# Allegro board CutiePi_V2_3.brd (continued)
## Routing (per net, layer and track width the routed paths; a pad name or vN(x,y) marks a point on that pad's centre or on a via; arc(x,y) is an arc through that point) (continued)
VBAT: length 21
  TOP w0.203: R3089.2 70.26,23.75 70.04,23.52 70.04,21.87 67.31,19.14 U597.17
  TOP w0.305: R3095.2 v1(57.82,23.88) ; R3100.2 v1(59.6,23.91)
  TOP w0.381: R3097.2 v1(72.55,12.06)
  L03 w0.508: v1(72.55,12.06) 72.55,13.37 v1(76.42,17.24) v1(77.44,17.24)
  vias: v1(68.2,27.43) v1(68.2,26.16) v1(69.47,27.43) v1(69.47,26.16) v1(70.74,44.07) v1(70.74,27.43) v1(70.74,26.16) v1(70.76,43.18) v1(71.77,44.06) v1(71.77,43.18) v1(72.01,27.43) v1(72.01,26.16)
VBAT_AD: length 8.9
  TOP w0.381: U18.14 62.7,41.46 63.01,41.15 65.02,41.15 65.63,41.75 R3053.1 C2525.1 R3154.1 R3052.1
VBAT_AD_C: length 69.4
  TOP w0.152: J24.94 54.66,97.84 51.94,95.12 51.94,80.14 v1(52.7,79.38) ; R3154.2 v1(68.85,43.29)
  L04 w0.145: v1(68.85,43.29) 68.85,43.93 65.79,46.99 58.56,46.99 57.4,48.14 57.4,50.55 53.09,54.86 53.09,76.33 53.34,76.58 53.34,78.74 v1(52.7,79.38)
VBUS: length 29.2
  TOP w0.305: R3101.1 v1(70.77,14.1) ; R3137.1 74.45,14.19 v1(74.36,14.1) 74.45,14 R3086.1
  TOP w0.381: v1(11.43,87.88) R3168.2 R3169.2 v1(11.43,86.36)
  TOP w0.508: FB9.2 29.09,17.05 v1(29.88,16.26)
  L04 w0.305: v1(63.5,9.91) 64.77,11.18 72.9,11.18 74.36,12.64 v1(74.36,14.1) 73.72,14.73 71.41,14.73 v1(70.77,14.1)
  vias: v1(12.7,81.66) v1(12.7,80.64) v1(12.7,79.63) v1(13.97,81.66) v1(13.97,80.64) v1(13.97,79.63) v1(15.37,81.66) v1(15.37,80.64) v1(15.37,79.63) v1(19.68,53.34) v1(19.68,52.07) v1(20.95,53.34) v1(20.95,52.07) v1(29.88,15.24) v1(30.89,16.26) v1(30.89,15.24) v1(31.91,16.26) v1(31.91,15.24) v1(61.37,4.36) v1(61.37,3.56) v1(62.39,4.36) v1(62.39,3.56) v1(63.41,4.36) v1(63.41,3.56) v1(67.56,93.09) v1(68.2,93.85) v1(68.45,104.52) v1(68.45,103.25) v1(68.45,101.98) v1(68.83,93.09) v1(69.72,104.52) v1(69.72,101.98)
VBUSA: length 5.9
  TOP w0.305: v1(15.78,45.21) 16.13,45.56 16.13,45.63 ; 16.13,45.63 v1(16.54,45.21) ; 16.13,45.63 U5.5
  TOP w0.381: R3058.2 8.67,88.36 v1(8.26,88.77)
  TOP w0.762: 12.1,49.98 J14.1 ; J14.1 12.1,51.92 ; J14.1 13.07,50.95
  vias: v1(16.51,55.88) v1(16.51,54.61) v1(17.78,55.88) v1(17.78,54.61) v1(39.12,44.96) v1(40.01,44.96)
VDDA: length 7
  TOP w0.305: FB7.2 66.44,34.44 C2479.1 C2474.1 63.74,34.87 63.43,35.18 62.21,35.18 61.4,35.99 U18.5
AMP_SHUTDOWN: length 44.8
  TOP w0.152: J24.45 60.22,88.24 60.71,87.76 61.72,87.76 v1(62.23,88.27) ; v1(74.93,104.78) 74.55,105.16 67.56,105.16 TP59.1
  TOP w0.254: R3145.1 64.96,100.87 R3061.2 ; R3061.2 66.97,100.87 67.06,100.96 Q6.1 ; R3061.2 66.29,101.6 66.42,101.73 66.42,103.25 TP59.1
  L03 w0.145: v1(74.93,104.78) 75.31,104.39 75.31,94.74 70.1,89.53 63.5,89.53 v1(62.23,88.27)
AU_IN: length 139.8
  TOP w0.152: R3184.2 C2517.2 37.59,17.4 v1(37.59,17.4) ; v1(69.85,93.34) 69.85,93.73 69.06,94.52 R127.1
  L04 w0.145: v1(69.85,93.34) 69.85,89.79 70.99,88.65 70.99,79.63 82.55,68.07 82.55,43.05 78.99,39.5 78.99,10.6 76.77,8.38 60.33,8.38 59.56,9.14 56.13,9.14 54.23,11.05 43.94,11.05 v1(37.59,17.4)
BL_EN: length 103.2
  TOP w0.152: R3197.1 64.11,84.45 v1(62.23,84.45) ; v1(42.45,17.02) R88.2
  L03 w0.145: v1(52.7,89.53) 53.34,90.17 55.75,90.17 56.13,89.79 56.13,86.87 56.64,86.36 59.69,86.36 60.58,85.47 61.21,85.47 v1(62.23,84.45)
  L04 w0.145: v1(42.45,17.02) 41.02,17.02 33.15,24.89 33.15,35.05 35.31,37.21 35.31,73.41 51.44,89.53 v1(52.7,89.53)
BOOST_EN: length 46.7
  TOP w0.152: v1(65.42,44.19) 64.65,43.42 U18.11 ; v1(59.1,16.65) 59.75,16 61.76,16 62.04,16.29 R3094.1 63.13,16.64 63.8,15.97 U597.24
  L04 w0.145: v1(65.42,44.19) 64.91,44.7 64.91,45.45 64.52,45.85 60.96,45.85 56.9,41.78 56.9,35.69 56.13,34.92 56.13,19.62 v1(59.1,16.65)
BT_NDIS: length 3
  TOP w0.152: J24.91 61.75,97.44 TP78.1
CAM0_CN: length 80.1
  TOP w0.109: v1(70.64,108.17) 70.87,108.4 70.87,108.58 70.77,108.68 J26.8 ; v1(20.32,86.86) 20.54,87.08 21.66,87.08 21.7,87.04 J25.40
  L03 w0.114: v1(20.32,86.86) 20.51,87.05 20.96,87.05 21.29,87.37 21.29,92.76 17.4,96.65 17.4,100.7 21.65,104.95 58.56,104.95 63.7,110.1 64.01,110.1 64.24,110.33 64.24,110.64 64.47,110.87 65.15,110.87 65.37,110.66 65.7,110.66 65.91,110.87 66.29,110.87 66.51,110.66 66.84,110.66 67.06,110.87 70.48,110.87 70.85,110.5 70.85,108.38 v1(70.64,108.17)
CAM0_CP: length 80.1
  TOP w0.109: v1(20.32,87.62) 20.54,87.4 21.66,87.4 21.7,87.44 J25.42 ; v1(71.4,108.17) 71.19,108.37 71.19,108.53 71.27,108.61 J26.9
  L03 w0.114: v1(71.4,108.17) 71.18,108.38 71.18,110.64 70.62,111.2 64.34,111.2 58.42,105.28 21.51,105.28 17.07,100.84 17.07,96.51 20.95,92.62 20.95,87.5 20.83,87.38 20.57,87.38 v1(20.32,87.62)
CAM0_DN0: length 80.3
  TOP w0.109: J26.2 67.77,108.64 67.86,108.54 67.86,108.39 v1(67.64,108.17) ; v1(20.32,84.46) 20.54,84.68 21.66,84.68 21.7,84.64 J25.28
  L03 w0.114: v1(20.32,84.46) 20.57,84.46 20.87,84.75 21.76,84.75 22.43,85.42 22.43,93.14 18.54,97.03 18.54,100.2 21.77,103.43 59.03,103.43 59.25,103.21 59.58,103.21 59.79,103.43 60.12,103.43 60.88,104.19 61.04,104.19 61.38,103.85 61.81,103.85 62.25,104.29 62.25,104.72 61.91,105.06 61.91,105.22 62.16,105.46 62.32,105.46 62.65,105.13 63.09,105.13 63.53,105.56 63.53,106 63.19,106.33 63.19,106.5 63.43,106.74 63.59,106.74 63.93,106.4 64.36,106.4 64.8,106.84 64.8,107.27 64.46,107.61 64.46,107.77 64.62,107.92 64.91,107.92 65.05,108.07 65.05,108.36 65.66,108.97 65.99,108.97 66.21,108.75 66.54,108.75 66.75,108.97 67.73,108.97 67.85,108.85 67.85,108.38 v1(67.64,108.17)
CAM0_DN1: length 81.7
  TOP w0.109: J25.34 22.84,85.84 22.88,85.88 23.91,85.88 v1(24.13,85.66) ; J26.5 69.27,108.6 69.35,108.52 69.35,107.28 v1(69.14,107.06)
  L03 w0.114: v1(69.14,107.06) 69.35,106.85 69.35,106.18 69.04,105.87 65.74,105.87 62.05,102.18 58.18,102.18 57.87,101.88 57.87,101.28 57.75,101.17 57.41,101.17 57.3,101.28 57.3,101.88 56.99,102.18 56.37,102.18 56.07,101.88 56.07,101.28 55.95,101.17 55.61,101.17 55.49,101.28 55.49,101.88 55.19,102.18 54.57,102.18 54.26,101.88 54.26,101.28 54.15,101.17 53.8,101.17 53.69,101.28 53.69,101.88 53.38,102.18 52.77,102.18 52.46,101.88 52.46,101.28 52.34,101.17 52,101.17 51.89,101.28 51.89,101.88 51.58,102.18 21.71,102.18 19.43,99.91 19.43,97.2 22.39,94.23 23.54,94.23 24.05,93.72 24.05,88.15 23.16,87.26 23.16,86.18 23.47,85.88 23.91,85.88 v1(24.13,85.66)
CAM0_DP0: length 80.3
  TOP w0.109: v1(68.4,108.17) 68.18,108.38 68.18,108.57 68.27,108.65 J26.3 ; v1(20.32,85.22) 20.54,85 21.66,85 21.7,85.04 J25.30
  L03 w0.114: v1(68.4,108.17) 68.18,108.38 68.18,108.98 67.87,109.3 65.52,109.3 64.13,107.91 64.13,107.47 64.47,107.14 64.47,106.97 64.23,106.73 64.07,106.73 63.73,107.07 63.29,107.07 62.86,106.63 62.86,106.2 63.19,105.86 63.19,105.7 62.95,105.46 62.79,105.46 62.45,105.79 62.02,105.79 61.58,105.36 61.58,104.92 61.92,104.59 61.92,104.42 61.68,104.18 61.52,104.18 61.18,104.52 60.74,104.52 59.99,103.76 21.63,103.76 18.21,100.34 18.21,96.89 22.1,93 22.1,85.56 21.62,85.08 20.71,85.08 20.57,85.22 v1(20.32,85.22)
CAM0_DP1: length 81.7
  TOP w0.109: J26.6 69.77,108.6 69.68,108.52 69.68,107.28 v1(69.9,107.06) ; J25.36 22.84,86.24 22.88,86.2 23.91,86.2 v1(24.13,86.42)
  L03 w0.114: v1(24.13,86.42) 23.91,86.21 23.61,86.21 23.5,86.32 23.5,87.12 24.38,88.01 24.38,93.85 23.67,94.56 22.53,94.56 19.76,97.33 19.76,99.77 21.84,101.85 51.44,101.85 51.56,101.74 51.56,101.15 51.86,100.84 52.48,100.84 52.79,101.15 52.79,101.74 52.9,101.85 53.25,101.85 53.36,101.74 53.36,101.15 53.67,100.84 54.28,100.84 54.59,101.15 54.59,101.74 54.71,101.85 55.05,101.85 55.16,101.74 55.16,101.15 55.47,100.84 56.09,100.84 56.4,101.15 56.4,101.74 56.51,101.85 56.85,101.85 56.97,101.74 56.97,101.15 57.27,100.84 57.89,100.84 58.2,101.15 58.2,101.74 58.31,101.85 62.19,101.85 65.1,104.76 65.41,104.76 65.64,105 65.64,105.3 65.87,105.54 66.2,105.54 66.42,105.32 66.75,105.32 66.96,105.54 67.44,105.54 67.65,105.32 67.98,105.32 68.2,105.54 69.17,105.54 69.68,106.05 69.68,106.85 v1(69.9,107.06)
CAM0_IO0: length 40.9
  TOP w0.152: J24.27 59.88,84.64 60.07,84.45 v1(60.96,84.45) ; v1(74.93,106.05) 75.27,106.38 J26.17
  L03 w0.145: v1(60.96,84.45) 61.34,84.45 61.85,83.95 63.12,83.95 65.66,86.49 67.31,86.49 68.96,88.14 75.18,88.14 77.22,90.17 77.22,102.62 76.07,103.76 76.07,104.9 v1(74.93,106.05)
CAM0_IO1: length 48
  TOP w0.152: v1(55.24,84.2) 55.29,84.24 J24.26 ; v1(76.2,106.05) 75.77,106.48 J26.18
  L03 w0.145: v1(76.2,106.05) 76.77,105.47 76.77,104.33 77.72,103.38 77.72,88.65 73.79,84.71 67.06,84.71 66.29,83.95 64.52,83.95 63.12,82.55 60.2,82.55 59.56,83.19 58.17,83.19 57.53,83.82 55.63,83.82 v1(55.24,84.2)
CAM1_CN: length 85.9
  TOP w0.109: J11.8 83.8,80.75 83.71,80.66 82.99,80.66 v1(82.71,80.95) ; J25.27 25.92,84.64 25.96,84.68 30.02,84.68 30.61,85.27 33.44,85.27 v1(33.66,85.05)
  L03 w0.114: v1(82.71,80.95) 82.99,80.67 83.91,80.67 86.34,78.24 86.34,71.91 84.54,70.1 51.73,70.1 50.48,71.35 50.48,71.78 50.76,72.06 50.76,72.22 50.52,72.46 50.35,72.46 50.08,72.19 49.65,72.19 49.21,72.62 49.21,73.06 49.48,73.33 49.48,73.49 49.24,73.74 49.08,73.74 48.81,73.46 48.37,73.46 47.93,73.9 47.93,74.34 48.21,74.61 48.21,74.77 47.96,75.01 47.8,75.01 47.53,74.74 47.09,74.74 46.66,75.18 46.66,75.61 46.93,75.88 46.93,76.04 46.69,76.29 46.53,76.29 46.25,76.01 45.82,76.01 36.56,85.27 33.87,85.27 v1(33.66,85.05)
CAM1_CP: length 85.8
  TOP w0.109: J25.29 25.92,85.04 25.96,85 27.25,85 27.46,85.21 27.66,85.21 27.86,85 28.26,85 28.46,85.21 28.67,85.21 28.87,85 29.07,85 29.28,85.21 29.48,85.21 29.68,85 29.89,85 30.48,85.6 30.68,85.6 30.89,85.8 31.09,85.8 31.29,85.6 31.5,85.6 31.7,85.8 31.9,85.8 32.11,85.6 32.33,85.6 32.54,85.8 32.74,85.8 32.94,85.6 33.44,85.6 v1(33.66,85.82) ; J11.9 83.83,80.25 83.75,80.34 82.99,80.34 v1(82.71,80.06)
  L03 w0.114: v1(82.71,80.06) 82.99,80.34 83.78,80.34 86.01,78.1 86.01,72.04 84.4,70.43 51.87,70.43 50.81,71.49 50.81,71.65 51.09,71.92 51.09,72.36 50.65,72.79 50.22,72.79 49.94,72.52 49.78,72.52 49.54,72.76 49.54,72.92 49.81,73.2 49.81,73.63 49.38,74.07 48.94,74.07 48.67,73.79 48.51,73.79 48.26,74.04 48.26,74.2 48.54,74.47 48.54,74.91 48.1,75.34 47.67,75.34 47.39,75.07 47.23,75.07 46.99,75.31 46.99,75.47 47.26,75.75 47.26,76.18 46.83,76.62 46.39,76.62 46.12,76.34 45.96,76.34 36.7,85.6 33.87,85.6 v1(33.66,85.82)
CAM1_DN0: length 88.6
  TOP w0.109: J25.15 25.92,82.24 25.96,82.28 33.44,82.28 v1(33.66,82.06) ; v1(82.71,83.95) 83.04,83.62 83.39,83.62 83.44,83.66 83.73,83.66 83.81,83.75 J11.2
  L03 w0.114: v1(33.66,82.06) 33.87,82.28 35.2,82.28 49.61,67.87 85.65,67.87 88.37,70.59 88.37,79.43 84.14,83.66 82.99,83.66 v1(82.71,83.95)
CAM1_DN1: length 87.2
  TOP w0.109: J11.5 83.81,82.25 83.73,82.16 83.57,82.16 81.85,82.16 v1(81.57,82.45) ; J25.21 25.92,83.44 25.96,83.48 30.34,83.48 30.61,83.75 35.34,83.75 v1(35.56,83.53)
  L03 w0.114: v1(81.57,82.45) 81.85,82.16 83.99,82.16 87.36,78.79 87.36,71.23 85.14,69.01 51.04,69.01 36.31,83.75 35.78,83.75 v1(35.56,83.53)
CAM1_DN2: length 87.4
  TOP w0.109: v1(35.56,86.71) 35.34,86.92 30.23,86.92 29.19,85.88 25.96,85.88 25.92,85.84 J25.33 ; v1(81.57,79.45) 81.85,79.16 83.73,79.16 83.82,79.25 J11.11
  L03 w0.114: v1(81.57,79.45) 81.84,79.17 84.06,79.17 85.34,77.88 85.34,72.56 84.03,71.25 55.79,71.25 52.62,74.42 50.21,74.42 46.85,77.78 46.69,77.78 46.46,77.55 46.02,77.55 45.59,77.98 45.59,78.42 45.82,78.65 45.82,78.81 45.57,79.05 45.41,79.05 45.18,78.82 44.75,78.82 44.31,79.26 44.31,79.7 44.54,79.93 44.54,80.09 44.3,80.33 44.14,80.33 43.91,80.1 43.47,80.1 43.04,80.54 43.04,80.97 43.27,81.2 43.27,81.36 43.02,81.6 42.86,81.6 42.63,81.37 42.2,81.37 41.76,81.81 41.76,82.25 41.99,82.48 41.99,82.64 41.75,82.88 41.59,82.88 41.36,82.65 40.92,82.65 40.49,83.09 40.49,83.52 40.72,83.75 40.72,83.91 40.47,84.16 40.31,84.16 40.08,83.93 39.65,83.93 39.21,84.36 39.21,84.8 39.44,85.03 39.44,85.19 39.2,85.43 39.04,85.43 38.81,85.2 38.37,85.2 37.93,85.64 37.93,86.07 38.16,86.3 38.16,86.46 37.71,86.92 36.17,86.92 35.96,86.71 v1(35.56,86.71)
CAM1_DN3: length 87.1
  TOP w0.109: v1(82.84,77.95) 83.12,77.66 83.73,77.66 83.81,77.75 J11.14 ; v1(33.66,88.23) 33.44,88.45 29.98,88.45 28.61,87.08 25.96,87.08 25.92,87.04 J25.39
  L03 w0.114: v1(82.84,77.95) 83.11,77.67 83.86,77.67 84.45,77.08 84.45,74.69 83.86,74.1 82.61,74.1 81.08,72.57 56.76,72.57 53.51,75.82 50.71,75.82 44.49,82.04 44.49,82.48 45.33,83.32 45.33,83.48 45.09,83.73 44.93,83.73 44.09,82.88 43.65,82.88 43.21,83.32 43.21,83.75 44.06,84.6 44.06,84.76 43.82,85 43.66,85 42.81,84.16 42.38,84.16 41.94,84.59 41.94,85.03 42.78,85.87 42.78,86.03 42.54,86.28 42.38,86.28 41.54,85.43 41.1,85.43 40.66,85.87 40.66,86.3 41.51,87.15 41.51,87.31 41.27,87.55 41.1,87.55 40.26,86.71 39.83,86.71 39.39,87.14 39.39,87.58 40.23,88.42 40.23,88.59 39.99,88.83 39.83,88.83 38.98,87.98 38.55,87.98 38.09,88.45 34.27,88.45 34.05,88.23 v1(33.66,88.23)
CAM1_DP0: length 88.6
  TOP w0.109: v1(82.71,83.06) 82.94,83.29 83.53,83.29 83.57,83.34 83.73,83.34 83.81,83.25 J11.3 ; J25.17 25.92,82.64 25.96,82.6 27.75,82.6 27.95,82.81 28.15,82.81 28.36,82.6 28.56,82.6 28.76,82.81 28.97,82.81 29.17,82.6 29.37,82.6 29.58,82.81 29.78,82.81 29.98,82.6 30.19,82.6 30.39,82.81 30.59,82.81 30.79,82.6 31,82.6 31.2,82.81 31.4,82.81 31.61,82.6 31.81,82.6 32.01,82.81 32.22,82.81 32.42,82.6 32.62,82.6 32.83,82.81 33.03,82.81 33.23,82.6 33.44,82.6 v1(33.66,82.82)
  L03 w0.114: v1(82.71,83.06) 82.99,83.33 84,83.33 88.04,79.29 88.04,70.73 85.51,68.2 49.74,68.2 35.34,82.61 33.87,82.61 v1(33.66,82.82)
CAM1_DP1: length 87.1
  TOP w0.109: v1(81.57,81.56) 81.85,81.84 83.44,81.84 83.73,81.84 83.81,81.75 J11.6 ; J25.23 25.92,83.84 25.96,83.8 28.58,83.8 28.79,84.01 28.99,84.01 29.19,83.8 29.4,83.8 29.6,84.01 29.8,84.01 30.01,83.8 30.21,83.8 30.48,84.07 30.68,84.07 30.89,84.28 31.09,84.28 31.29,84.07 31.5,84.07 31.7,84.28 31.9,84.28 32.11,84.07 32.31,84.07 32.51,84.28 32.72,84.28 32.92,84.07 33.12,84.07 33.32,84.28 33.53,84.28 33.73,84.07 35.34,84.07 v1(35.56,84.29)
  L03 w0.114: v1(81.57,81.56) 81.84,81.83 83.85,81.83 87.03,78.65 87.03,71.37 85,69.34 51.18,69.34 36.45,84.08 35.78,84.08 v1(35.56,84.29)
CAM1_DP2: length 87.3
  TOP w0.109: v1(81.57,78.56) 81.85,78.84 83.72,78.84 83.81,78.75 J11.12 ; J25.35 25.92,86.24 25.96,86.2 29.05,86.2 29.5,86.65 29.5,86.94 29.65,87.08 29.93,87.08 30.1,87.25 30.3,87.25 30.51,87.45 30.71,87.45 30.91,87.25 31.11,87.25 31.32,87.45 31.52,87.45 31.72,87.25 31.93,87.25 32.13,87.45 32.33,87.45 32.54,87.25 32.74,87.25 32.94,87.45 33.15,87.45 33.35,87.25 33.55,87.25 33.76,87.45 33.96,87.45 34.16,87.25 35.34,87.25 v1(35.56,87.47)
  L03 w0.114: v1(81.57,78.56) 81.85,78.84 83.92,78.84 85.01,77.75 85.01,72.69 83.9,71.58 55.93,71.58 52.76,74.75 50.34,74.75 46.99,78.11 46.55,78.11 46.32,77.88 46.16,77.88 45.92,78.12 45.92,78.28 46.15,78.51 46.15,78.95 45.71,79.38 45.28,79.38 45.05,79.15 44.88,79.15 44.64,79.4 44.64,79.56 44.87,79.79 44.87,80.22 44.44,80.66 44,80.66 43.77,80.43 43.61,80.43 43.37,80.67 43.37,80.83 43.6,81.06 43.6,81.5 43.16,81.94 42.72,81.94 42.49,81.7 42.33,81.71 42.09,81.95 42.09,82.11 42.32,82.34 42.32,82.77 41.88,83.21 41.45,83.21 41.22,82.98 41.06,82.98 40.82,83.22 40.82,83.38 41.05,83.61 41.05,84.05 40.61,84.49 40.17,84.49 39.94,84.26 39.78,84.26 39.54,84.5 39.54,84.66 39.77,84.89 39.77,85.32 39.33,85.76 38.9,85.76 38.67,85.53 38.51,85.53 38.26,85.77 38.26,85.93 38.49,86.17 38.49,86.6 37.84,87.25 36.17,87.25 35.96,87.47 v1(35.56,87.47)
CAM1_DP3: length 87
  TOP w0.109: v1(82.84,77.06) 83.12,77.34 83.44,77.34 83.73,77.34 83.81,77.25 J11.15 ; v1(33.66,88.99) 33.44,88.77 33.1,88.77 32.89,88.98 32.69,88.98 32.49,88.77 32.28,88.77 32.08,88.98 31.88,88.98 31.67,88.77 31.47,88.77 31.27,88.98 31.06,88.98 30.86,88.77 30.66,88.77 30.45,88.98 30.25,88.98 30.05,88.77 29.84,88.77 29.7,88.63 29.41,88.63 29.27,88.49 29.27,88.2 29.13,88.05 28.84,88.05 28.7,87.91 28.7,87.62 28.48,87.4 25.96,87.4 25.92,87.44 J25.41
  L03 w0.114: v1(82.84,77.06) 83.12,77.34 83.73,77.34 84.12,76.94 84.12,74.83 83.72,74.43 82.47,74.43 80.94,72.9 56.9,72.9 53.64,76.15 50.85,76.15 44.82,82.18 44.82,82.34 45.66,83.19 45.66,83.62 45.23,84.06 44.79,84.06 43.95,83.21 43.79,83.21 43.55,83.45 43.55,83.62 44.39,84.46 44.39,84.9 43.95,85.33 43.52,85.33 42.67,84.49 42.51,84.49 42.27,84.73 42.27,84.89 43.11,85.74 43.11,86.17 42.68,86.61 42.24,86.61 41.4,85.76 41.24,85.76 40.99,86.01 40.99,86.17 41.84,87.01 41.84,87.45 41.4,87.88 40.97,87.88 40.12,87.04 39.96,87.04 39.72,87.28 39.72,87.44 40.56,88.29 40.56,88.72 40.13,89.16 39.69,89.16 38.85,88.31 38.69,88.31 38.22,88.78 34.27,88.78 34.05,88.99 v1(33.66,88.99)
CAM1_IO0: length 36.5
  TOP w0.152: J11.17 83.87,76.25 83.82,76.2 80.01,76.2 v1(80.01,76.2) ; J24.34 55.36,85.84 v1(55.24,85.72)
  L03 w0.145: v1(55.24,85.72) 54.74,85.22 54.74,82.93 55.12,82.55 56.39,82.55 57.66,81.28 59.69,81.28 60.07,80.9 75.31,80.9 v1(80.01,76.2)
CAM1_IO1: length 42.2
  TOP w0.152: J11.18 82.1,75.75 81.92,75.56 79.38,75.56 v1(78.74,76.2) ; v1(55.24,89.53) 55.55,89.84 J24.54
  L03 w0.145: v1(78.74,76.2) 74.55,80.39 60.96,80.39 60.58,80.01 57.91,80.01 56.64,81.28 54.99,81.28 54.23,82.04 54.23,86.11 54.61,86.49 54.61,88.9 v1(55.24,89.53)
CAM_GPIO: length 4.1
  TOP w0.152: J24.97 60.16,98.64 61.21,99.69 61.21,100.2 TP79.1
CHARGE_EN: length 43.6
  TOP w0.152: U18.12 64,44.04 v1(64.15,44.19) ; v1(59.1,15.38) 59.75,14.73 61.76,14.73 62.04,15.02 R3096.1 62.24,15.57 U597.25
  L04 w0.145: v1(59.1,15.38) 59.72,16 59.72,16.98 56.77,19.94 56.77,34.8 58.29,36.32 58.29,41.15 61.85,44.7 63.64,44.7 v1(64.15,44.19)
CM_1V8: length 2.7
  TOP w0.305: v1(89.15,41.15) 88.91,40.9 J21.3 v1(87.43,40.9)
  TOP w0.381: R3057.1 v1(83.09,40.39)
  vias: v1(57.15,97.16) v1(58.42,97.16) v1(80.01,107.31) v1(80.01,106.05) v1(81.28,107.31) v1(81.28,106.05)
CM_3V3: length 13.5
  TOP w0.254: v1(80.01,74.93) 80.14,74.8 R16.1 ; C385.1 74.07,89.72 74.01,89.66 U57.13 ; R17.1 80.26,73.41 v1(80.01,73.66)
  TOP w0.305: R3167.1 v1(78.23,90.42) ; J21.1 87.09,41.5 86.79,41.2 J21.2 v1(84.58,41.2) v1(83.82,41.2) ; v1(78.11,107.95) 77.77,108.29 J26.22 ; R370.1 v1(78.23,84.07) ; v1(74.93,90.17) C385.1
  TOP w0.381: R3165.2 v1(67.44,85.34) ; R3166.2 v1(67.44,84.07)
  vias: v1(14.1,86.49) v1(15.24,86.49) v1(15.24,85.47) v1(53.98,95.89) v1(55.24,95.89) v1(57.15,95.89) v1(58.42,95.89) v1(62.23,90.81) v1(63.5,92.08) v1(63.5,90.81) v1(82.8,73.15) v1(83.44,72.52) v1(84.07,73.15)
DSI1_CN: length 108.5
  TOP w0.109: v1(86.36,37.46) 86.22,37.6 J21.14 ; v1(30.23,96.5) 30.08,96.65 28.96,96.65 28.89,96.72 25.99,96.72 25.92,96.64 J25.87
  L03 w0.114: v1(30.23,96.5) 30.01,96.71 29.49,96.71 29.34,96.56 29.34,92.46 30.05,91.74 30.05,80.19 48.46,61.77 48.46,58.22 56.08,50.6 56.08,48.06 61.85,42.29 71.75,42.29 72.41,41.64 72.57,41.64 72.97,42.04 73.4,42.04 73.84,41.6 73.84,41.17 73.44,40.77 73.44,40.61 73.68,40.36 73.84,40.36 74.24,40.76 74.68,40.76 75.11,40.33 75.11,39.89 74.71,39.49 74.71,39.33 74.96,39.09 75.12,39.09 75.52,39.49 75.95,39.49 76.39,39.05 76.39,38.62 75.99,38.22 75.99,38.06 76.96,37.08 78.54,37.08 78.75,37.29 78.95,37.29 79.15,37.08 79.36,37.08 79.56,37.29 79.76,37.29 79.97,37.08 80.17,37.08 80.39,37.3 80.61,37.3 80.83,37.08 81.06,37.08 81.27,37.3 81.5,37.3 81.72,37.08 81.95,37.08 82.16,37.3 82.39,37.3 82.61,37.08 82.84,37.08 83.05,37.3 83.28,37.3 83.5,37.08 83.73,37.08 83.94,37.3 84.17,37.3 84.39,37.08 84.62,37.08 84.83,37.3 85.06,37.3 85.28,37.08 85.5,37.08 85.64,36.95 86.62,36.95 86.74,37.07 86.74,37.35 86.62,37.46 v1(86.36,37.46)
DSI1_CP: length 108.6
  TOP w0.109: v1(87.24,37.46) 87.4,37.3 J21.15 ; J25.89 29.02,97.04 29.09,96.97 29.94,96.97 v1(30.23,97.26)
  L03 w0.114: v1(87.24,37.46) 87.07,37.28 87.07,36.93 86.76,36.62 85.5,36.62 85.37,36.75 76.83,36.75 75.66,37.92 75.66,38.35 76.06,38.75 76.06,38.92 75.82,39.16 75.66,39.16 75.26,38.76 74.82,38.76 74.38,39.19 74.38,39.63 74.78,40.03 74.78,40.19 74.54,40.43 74.38,40.43 73.98,40.03 73.54,40.03 73.11,40.47 73.11,40.91 73.51,41.31 73.51,41.47 73.27,41.71 73.1,41.71 72.7,41.31 72.27,41.31 71.62,41.96 61.71,41.96 55.75,47.92 55.75,50.46 48.13,58.08 48.13,61.64 29.72,80.05 29.72,91.61 29.01,92.32 29.01,96.7 29.35,97.04 30.01,97.04 v1(30.23,97.26)
DSI1_DN0: length 108.6
  TOP w0.109: v1(87.25,38.86) 87.12,38.86 86.96,38.7 86.96,38.38 87.1,38.25 87.53,38.25 87.78,38.5 J21.11 ; J25.75 25.92,94.24 25.96,94.28 26.12,94.28 26.37,94.02 30.18,94.02 v1(30.35,93.85)
  L03 w0.114: v1(30.35,93.85) 30.57,94.07 31.05,94.07 31.5,93.62 31.5,80.43 49.4,62.53 49.4,58.84 58.79,49.45 69.93,49.45 75.26,44.12 75.26,43.96 74.54,43.24 74.54,42.81 74.98,42.37 75.41,42.37 76.13,43.09 76.29,43.09 76.53,42.85 76.53,42.69 75.82,41.97 75.82,41.53 76.25,41.1 76.69,41.1 77.4,41.81 77.57,41.81 78.31,41.07 78.31,38.33 78.62,38.02 79.23,38.02 79.54,38.33 79.54,40.32 79.66,40.44 80,40.44 80.11,40.32 80.11,38.33 80.42,38.02 86.59,38.02 86.9,38.33 86.9,38.64 87.12,38.86 v1(87.25,38.86)
DSI1_DN1: length 107.8
  TOP w0.109: v1(27.3,95.25) 27.12,95.43 25.87,95.43 25.86,95.44 J25.81 ; J21.17 87.19,36.7 86.99,36.5 86.99,36.16 87.09,36.06 v1(87.24,36.06)
  L03 w0.114: v1(27.3,95.25) 27.52,95.47 27.75,95.47 27.86,95.35 27.86,91.3 28.45,90.72 28.45,87.06 28.33,86.95 27.61,86.95 27.3,86.64 27.3,86.02 27.61,85.72 28.33,85.72 28.45,85.6 28.45,85.26 28.33,85.14 27.61,85.14 27.3,84.84 27.3,84.22 27.61,83.91 28.33,83.91 28.45,83.8 28.45,83.46 28.33,83.34 27.61,83.34 27.3,83.03 27.3,82.42 27.61,82.11 28.33,82.11 28.45,81.99 28.45,79.54 46.23,61.76 46.23,55.03 61,40.26 70.61,40.26 75.65,35.23 86.66,35.23 87.03,35.59 87.03,35.85 v1(87.24,36.06)
DSI1_DN2: length 109.1
  TOP w0.109: J25.93 25.92,97.84 25.96,97.88 26.33,97.88 v1(26.54,97.66) ; J21.20 85.86,35.8 86.23,35.43 86.56,35.43 86.66,35.32 86.66,34.78 86.56,34.67 v1(86.36,34.67)
  L03 w0.114: v1(26.54,97.66) 26.33,97.88 25.74,97.88 25.48,97.61 25.48,80.19 45.34,60.33 45.34,52.83 60.96,37.21 71.59,37.21 74.89,33.91 79.59,33.91 79.8,34.12 80.03,34.12 80.25,33.91 80.47,33.91 80.69,34.12 80.92,34.12 81.14,33.91 81.36,33.91 81.58,34.12 81.81,34.12 82.02,33.91 82.25,33.91 82.47,34.12 82.7,34.12 82.91,33.91 83.14,33.91 83.36,34.12 83.59,34.12 83.8,33.91 84.03,33.91 84.25,34.12 84.48,34.12 84.69,33.91 85.17,33.91 85.39,34.12 85.62,34.12 85.83,33.91 86.23,33.91 86.7,34.38 86.7,34.55 86.59,34.67 v1(86.36,34.67)
DSI1_DN3: length 108.7
  TOP w0.109: v1(86.36,40.01) 86.61,40.01 86.74,39.88 86.74,39.55 86.59,39.4 J21.8 ; v1(20.32,97.66) 20.54,97.88 21.66,97.88 21.7,97.84 J25.94
  L03 w0.114: v1(86.36,40.01) 86.67,40.32 86.67,40.45 85.09,42.04 79.04,42.04 69.84,51.23 59.05,51.23 51.82,58.46 51.82,61.85 32.44,81.23 32.44,97.65 30.14,99.95 24.51,99.95 23.02,98.45 23.02,98.17 22.87,98.02 22.58,98.02 22.44,97.88 22.15,97.88 21.95,97.68 21.74,97.68 21.54,97.88 20.54,97.88 v1(20.32,97.66)
DSI1_DP0: length 108.7
  TOP w0.109: v1(30.35,94.61) 30.09,94.35 29.88,94.35 29.68,94.55 29.48,94.55 29.27,94.35 29.07,94.35 28.87,94.55 28.67,94.55 28.46,94.35 28.12,94.35 27.91,94.55 27.71,94.55 27.51,94.35 26.51,94.35 26.25,94.6 25.96,94.6 25.92,94.64 J25.77 ; J21.12 86.53,38.2 86.64,38.31 86.64,38.58 v1(86.36,38.86)
  L03 w0.114: v1(86.36,38.86) 86.57,38.66 86.57,38.47 86.45,38.35 85.33,38.35 85.11,38.57 84.88,38.57 84.67,38.35 83.93,38.35 83.71,38.57 83.48,38.57 83.27,38.35 80.56,38.35 80.44,38.47 80.44,40.46 80.14,40.77 79.52,40.77 79.21,40.46 79.21,38.47 79.1,38.35 78.75,38.35 78.64,38.47 78.64,41.21 77.7,42.14 77.27,42.14 76.55,41.43 76.39,41.43 76.15,41.67 76.15,41.83 76.86,42.55 76.86,42.98 76.43,43.42 75.99,43.42 75.27,42.7 75.11,42.7 74.87,42.94 74.87,43.11 75.59,43.82 75.59,44.26 70.06,49.78 58.93,49.78 49.73,58.98 49.73,62.66 31.83,80.57 31.83,93.76 31.19,94.4 30.57,94.4 v1(30.35,94.61)
DSI1_DP1: length 107.7
  TOP w0.109: v1(27.3,96.01) 27.05,95.76 26,95.76 25.92,95.84 J25.83 ; v1(86.36,36.06) 86.6,36.06 86.66,36.13 86.66,36.59 86.56,36.7 86.23,36.7 85.93,36.4 J21.18
  L03 w0.114: v1(27.3,96.01) 27.52,95.8 27.89,95.8 28.19,95.49 28.19,91.44 28.78,90.86 28.78,86.93 28.47,86.62 27.75,86.62 27.64,86.5 27.64,86.16 27.75,86.05 28.47,86.05 28.78,85.74 28.78,85.12 28.47,84.81 27.75,84.81 27.64,84.7 27.64,84.36 27.75,84.24 28.47,84.24 28.78,83.94 28.78,83.32 28.47,83.01 27.75,83.01 27.64,82.9 27.64,82.55 27.75,82.44 28.47,82.44 28.78,82.13 28.78,79.68 46.56,61.9 46.56,55.17 61.14,40.59 70.75,40.59 75.78,35.56 86.52,35.56 86.7,35.73 86.7,35.95 86.58,36.06 v1(86.36,36.06)
DSI1_DP2: length 109.2
  TOP w0.109: J21.21 87.19,35.5 86.99,35.3 86.99,34.78 87.1,34.67 v1(87.24,34.67) ; v1(26.54,98.42) 26.32,98.2 25.96,98.2 25.92,98.24 J25.95
  L03 w0.114: v1(87.24,34.67) 87.03,34.46 87.03,34.24 86.37,33.58 74.75,33.58 71.45,36.88 60.82,36.88 45.01,52.7 45.01,60.19 25.15,80.05 25.15,97.75 25.61,98.21 26.33,98.21 v1(26.54,98.42)
DSI1_DP3: length 108.7
  TOP w0.109: v1(87.28,40.01) 87.16,40.01 87.07,39.92 87.07,39.56 87.2,39.42 87.5,39.42 87.82,39.1 J21.9 ; J25.96 21.7,98.24 21.66,98.2 20.54,98.2 v1(20.32,98.42)
  L03 w0.114: v1(87.28,40.01) 87,40.28 87,40.59 85.23,42.37 79.17,42.37 69.98,51.56 59.18,51.56 52.15,58.6 52.15,61.99 32.77,81.37 32.77,97.79 30.28,100.28 24.37,100.28 22.3,98.21 20.54,98.21 v1(20.32,98.42)
E2P_CS: length 10
  TOP w0.152: U580.1 38.73,40.26 37.72,41.27 35.81,41.27 34.67,40.13 34.67,39.12 33.35,37.79 U3.4
E2P_DI: length 4.1
  TOP w0.152: R3174.1 37.11,37.69 38.35,36.45 U580.4
E2P_DO: length 4.3
  TOP w0.152: R3175.1 37.72,39.53 37.72,38.23 38.23,37.72 U580.3
E2P_SK: length 10
  TOP w0.152: U580.2 38.48,38.99 38.23,39.24 38.23,40.01 37.47,40.77 35.94,40.77 35.18,40.01 35.18,38.99 33.85,37.66 U3.3
EEPROM_WP: length 10.6
  TOP w0.152: TP84.1 64.64,83.06 v1(64.52,82.93) ; J24.20 57.04,83.04 v1(57.15,82.93)
  L03 w0.145: v1(64.52,82.93) 62.99,81.41 60.33,81.41 59.18,82.55 57.53,82.55 v1(57.15,82.93)
GLOBAL_EN: length 8.2
  TOP w0.152: J24.99 59.93,99.04 60.58,99.69 60.58,100.71 61.98,102.11 R3193.2 64.11,103.6 TP80.1
GPIO12: length 7.1
  TOP w0.152: J24.31 62.01,85.44 62.36,85.09 63.75,85.09 64.26,85.6 65.28,85.6 65.43,85.45 R3197.2
GPIO13: length 55.4
  TOP w0.152: v1(51.94,73.41) 54.61,76.07 54.61,84.33 54.99,84.71 55.5,84.71 55.57,84.64 J24.28 ; v1(14.61,78.36) 15.02,78.77 R3196.2 15.46,78.86 Q7.1
  BOTTOM w0.152: v1(51.94,73.41) 24.26,73.41 19.3,78.36 v1(14.61,78.36)
GPIO14: length 6
  TOP w0.152: J24.55 61.14,90.24 61.72,89.66 63.72,89.66 R3194.2
GPIO15: length 6.1
  TOP w0.152: R3195.2 63.09,89.03 60.71,89.03 60.29,89.44 J24.51
GPIO16: length 23.7
  TOP w0.152: R3201.2 64.96,99.54 64.96,97.34 v1(64.77,97.16) ; v1(66.17,84.84) 66.17,84.33 65.79,83.95 61.85,83.95 61.59,84.2 61.59,84.71 61.34,84.96 60.07,84.96 59.99,85.04 J24.29
  L04 w0.145: v1(64.77,97.16) 65.15,96.77 65.15,85.85 v1(66.17,84.84)
GPIO25: length 5.8
  TOP w0.152: R3198.2 63.5,87.35 60.48,87.35 60.39,87.44 J24.41
GPIO_VEF(IN): length 14.7
  TOP w0.152: J24.78 v1(55.24,94.64) ; R3157.2 v1(66.17,90.3)
  L03 w0.145: v1(66.17,90.3) 63.75,92.71 56.64,92.71 56.01,93.34 56.01,93.88 v1(55.24,94.64)
GYRO_INT: length 24
  TOP w0.152: v1(57.15,88.27) 56.77,88.64 J24.48 ; U57.12 75.23,87.93 75.44,88.14 75.44,88.39 v1(74.93,88.9) 74.93,89.15 76.2,90.42 R3167.2
  L03 w0.145: v1(57.15,88.27) 57.78,87.63 65.15,87.63 65.66,88.14 66.67,88.14 67.44,88.9 v1(74.93,88.9)
HDMI1_SCL: length 29.4
  TOP w0.152: v1(27.69,89.66) 27.05,89.03 26.29,89.03 25.9,88.64 J25.47 ; v1(10.03,87.12) 9.88,86.97 R3169.1 9.02,86.36 8.64,86.74 7.24,86.74 6.65,86.15 J13.17
  BOTTOM w0.152: v1(10.03,87.12) 15.62,87.12 16,86.74 17.14,86.74 18.03,87.63 19.56,87.63 20.08,88.16 21.7,88.16 22.35,87.5 23.62,87.5 24,87.88 24.64,87.88 25.27,87.25 27.3,87.25 28.19,88.14 28.19,89.15 v1(27.69,89.66)
HDMI1_SDA: length 34.2
  TOP w0.152: v1(8.26,90.42) 8.26,89.92 9.88,88.29 R3168.1 ; v1(26.42,88.39) 26.26,88.24 J25.45 ; v1(3.05,86.87) 3.17,86.74 3.94,86.74 4.33,86.35 J13.18
  L04 w0.145: v1(3.05,86.87) 3.68,86.87 4.06,86.49 6.35,86.49 7.37,87.5 7.37,89.53 v1(8.26,90.42)
  BOTTOM w0.152: v1(26.42,88.39) 23.88,90.93 22.61,90.93 22.35,91.19 18.67,91.19 18.41,90.93 8.76,90.93 v1(8.26,90.42)
HDMI_CEC: length 28.1
  TOP w0.152: v1(17.78,81.66) 16.76,82.68 14.1,82.68 12.29,84.48 R15.1 12.28,84.83 Q3.2 ; J25.49 25.79,89.04 v1(26.42,89.66)
  BOTTOM w0.152: v1(17.78,81.66) 19.43,83.31 24.89,83.31 28.7,87.12 28.7,89.53 27.94,90.3 27.05,90.3 v1(26.42,89.66)
HDMI_CK_N: length 26.6
  TOP w0.109: J25.66 21.7,92.24 21.66,92.2 20.4,92.2 20.02,92.58 19.23,92.58 v1(19.05,92.77) ; J13.14 4.06,85.55 3.85,85.77 3.11,85.77 v1(2.83,86.05)
  L03 w0.114: v1(19.05,92.77) 18.81,92.53 13.58,92.53 12.82,91.77 8.12,91.77 6.78,90.43 6.78,87.77 4.74,85.72 3.15,85.72 v1(2.83,86.05)
HDMI_CK_P: length 26.5
  TOP w0.109: v1(2.83,85.29) 2.98,85.44 3.71,85.44 4,85.15 J13.12 ; J25.64 21.7,91.84 21.66,91.88 20.26,91.88 19.88,92.26 19.3,92.26 v1(19.05,92.01)
  L03 w0.114: v1(19.05,92.01) 18.85,92.2 13.72,92.2 12.95,91.44 8.26,91.44 7.11,90.3 7.11,87.63 4.88,85.39 2.93,85.39 v1(2.83,85.29)
HDMI_D0_N: length 25.3
  TOP w0.109: J25.60 21.7,91.04 21.66,91 21.08,91 20.77,91.31 19.43,91.31 19.05,90.93 18.08,90.93 16.44,89.29 16.44,87.72 v1(16.22,87.5) ; J13.11 6.62,84.95 6.69,84.88 7.15,84.88 7.44,85.16 7.97,85.16 v1(8.2,85.4)
  L03 w0.114: v1(16.22,87.5) 16.44,87.29 16.44,85.27 15.7,84.53 13.5,84.53 13.38,84.65 13.38,85.14 13.08,85.45 12.46,85.45 12.15,85.14 12.15,84.65 12.04,84.53 11.69,84.53 11.58,84.65 11.58,85.26 11.27,85.57 10.66,85.57 10.35,85.26 10.35,84.65 10.23,84.53 9.89,84.53 9.78,84.65 9.78,84.88 9.47,85.19 8.41,85.19 v1(8.2,85.4)
HDMI_D0_P: length 25.3
  TOP w0.109: J25.58 21.7,90.64 21.66,90.68 20.95,90.68 20.64,90.99 19.57,90.99 19.18,90.61 18.22,90.61 16.76,89.15 16.76,87.72 v1(16.98,87.5) ; J13.9 7.29,84.55 7.57,84.84 8,84.84 v1(8.2,84.63)
  L03 w0.114: v1(8.2,84.63) 8.43,84.86 9.33,84.86 9.45,84.75 9.45,84.51 9.75,84.2 10.37,84.2 10.68,84.51 10.68,85.13 10.79,85.24 11.13,85.24 11.25,85.13 11.25,84.51 11.56,84.2 12.17,84.2 12.48,84.51 12.48,85 12.6,85.12 12.94,85.12 13.05,85 13.05,84.51 13.36,84.2 15.83,84.2 16.77,85.13 16.77,87.29 v1(16.98,87.5)
HDMI_D1_N: length 24.3
  TOP w0.109: J25.54 21.7,89.84 21.66,89.8 19.8,89.8 v1(19.56,90.04) ; v1(2.83,84.54) 3.1,84.28 4.09,84.28 4.16,84.35 J13.8
  L03 w0.114: v1(19.56,90.04) 19.38,89.87 10.91,89.87 7.79,86.74 7.28,86.74 4.83,84.29 3.08,84.29 v1(2.83,84.54)
HDMI_D1_P: length 24.2
  TOP w0.109: v1(19.56,89.28) 19.76,89.48 21.66,89.48 21.7,89.44 J25.52 ; v1(2.83,83.78) 2.99,83.95 J13.6
  L03 w0.114: v1(2.83,83.78) 3,83.96 4.97,83.96 7.42,86.41 7.92,86.41 11.05,89.53 19.3,89.53 v1(19.56,89.28)
HDMI_D2_N: length 24.3
  TOP w0.109: J25.48 21.7,88.64 21.66,88.6 19.69,88.6 18.47,87.38 18.47,86.07 v1(18.25,85.85) ; J13.5 6.82,83.75 6.85,83.71 7.09,83.71 7.29,83.51 8,83.51 v1(8.21,83.71)
  L03 w0.114: v1(18.25,85.85) 18.47,85.64 18.47,85.02 16.95,83.5 15.49,83.5 15.18,83.19 15.18,82.99 15.06,82.88 14.72,82.88 14.61,82.99 14.61,83.19 14.3,83.5 13.68,83.5 13.37,83.19 13.37,82.99 13.26,82.88 12.92,82.88 12.8,82.99 12.8,83.19 12.5,83.5 11.88,83.5 11.57,83.19 11.57,82.99 11.46,82.88 11.11,82.88 11,82.99 11,83.19 10.69,83.5 10.08,83.5 9.77,83.19 9.77,82.36 9.65,82.25 9.31,82.25 9.2,82.36 9.2,83.19 8.89,83.5 8.42,83.5 v1(8.21,83.71)
HDMI_D2_P: length 24.3
  TOP w0.109: v1(8.21,82.95) 7.97,83.19 7.16,83.19 6.96,83.39 6.85,83.39 6.82,83.35 J13.3 ; v1(19.01,85.85) 18.8,86.07 18.8,87.25 19.83,88.28 21.66,88.28 21.7,88.24 J25.46
  L03 w0.114: v1(19.01,85.85) 18.8,85.64 18.8,84.88 17.09,83.17 15.62,83.17 15.51,83.05 15.51,82.86 15.2,82.55 14.58,82.55 14.28,82.86 14.28,83.05 14.16,83.17 13.82,83.17 13.71,83.05 13.71,82.86 13.4,82.55 12.78,82.55 12.47,82.86 12.47,83.05 12.36,83.17 12.02,83.17 11.9,83.05 11.9,82.86 11.59,82.55 10.98,82.55 10.67,82.86 10.67,83.05 10.56,83.17 10.21,83.17 10.1,83.05 10.1,82.22 9.79,81.92 9.17,81.92 8.87,82.22 8.87,83.05 8.75,83.17 8.42,83.17 v1(8.21,82.95)
HDMI_HPD: length 13
  TOP w0.152: R3062.2 11.05,89.28 12.07,88.26 Q4.1 12.07,85.99 11.68,85.6 10.54,85.6 10.16,85.22 10.16,83.69 8.64,82.17 7.11,82.17 6.86,82.42 6.86,82.8 6.71,82.95 J13.1
HDMI_HPD_N: length 20.1
  TOP w0.152: v1(27.69,88.39) 27.13,87.84 J25.43 ; Q4.3 13.42,88.68 13.94,88.17 R18.1 15.02,88.17 v1(15.75,88.9)
  BOTTOM w0.152: v1(27.69,88.39) 27.05,87.76 26.04,87.76 24.13,89.66 22.35,89.66 21.44,88.75 19.94,88.75 19.46,88.27 18.41,88.27 17.78,88.9 v1(15.75,88.9)
ID_SC: length 4.1
  TOP w0.152: TP90.1 60.33,85.85 59.94,86.24 J24.35
ID_SD: length 8.5
  TOP w0.152: v1(62.23,83.19) 62.36,83.06 TP89.1 ; J24.36 56.63,86.24 v1(57.15,85.72)
  L03 w0.145: v1(62.23,83.19) 61.98,83.19 61.34,83.82 59.31,83.82 57.4,85.72 v1(57.15,85.72)
IN2SYS_EN: length 60.5
  TOP w0.152: v1(62.88,44.19) 63.35,43.73 U18.13 ; U597.7 67.71,12.97 70.26,10.41 70.26,9.31 70.43,9.14 R3093.1 70.87,9.62 71.15,9.91 72.39,9.91 73.15,9.14 R3092.2 73.63,9.62 73.91,9.91 75.82,9.91 v1(76.45,10.54)
  L04 w0.145: v1(62.88,44.19) 60.96,42.27 60.96,38.35 63.18,36.13 70.93,36.13 74.8,32.26 74.8,16.38 76.23,14.95 76.23,10.76 v1(76.45,10.54)
LCD_RST: length 79.5
  TOP w0.152: J21.5 v1(89.15,40.3) ; J24.30 55.68,85.04 55.63,85.09 54.61,85.09 53.98,84.45 v1(53.98,79.38) ; v1(80.64,43.69) 82.27,42.07 R3057.2
  L03 w0.145: v1(89.15,40.3) 88.52,40.94 88.52,41.76 86.59,43.69 v1(80.64,43.69)
  L04 w0.145: v1(80.64,43.69) 76.83,47.5 58.89,47.5 58.04,48.35 58.04,51.44 53.59,55.88 53.59,75.69 53.98,76.07 v1(53.98,79.38)
LED0: length 5
  TOP w0.254: R3178.1 26.8,38.73 27.84,37.69 29.59,37.69 29.85,37.44 U3.11
LEDR: length 2.8
  TOP w0.254: U3.19 25.54,32.02 R3179.1
LOL: length 2.8
  TOP w0.152: U3.30 31.85,26.45 32.13,26.16 C2518.1
LOR: length 4.1
  TOP w0.152: U3.32 32.85,26.97 34.55,25.27 C2516.1
MCU_3V3: length 30.4
  TOP w0.305: TP98.1 45.42,61.21 46.86,61.21 49.35,58.73 J7.1 49.35,52.58 49.37,52.55 R3043.1 ; C2477.1 61.41,46.07 61.1,46.37 61.1,48.64 61.74,49.28 R3051.1 ; U18.16 61.4,45.12 v1(61.61,45.33) ; v1(67.96,34.16) 67.9,34.22 R3060.1 ; v1(67.42,33.02) FB7.1 v1(66.53,32.13) ; R272.2 v1(62.47,32.89) ; R3040.2 v1(56.01,40.16)
  TOP w0.381: R3043.1 v1(47.62,51.82)
  vias: v1(8.13,101.09) v1(8.13,100.2) v1(62.88,45.33) v1(64.15,45.33) v1(65.42,45.33)
MCU_IND: length 4.8
  TOP w0.152: U18.9 64,37.71 64.38,38.1 65.03,38.1 65.51,37.62 R3059.2 67.6,37.62 Q5.1
MCU_REV1: length 95.7
  TOP w0.152: U18.6 62.05,38.41 v1(61.72,38.73) ; R3193.1 v1(65.79,102.11) ; R3198.1 65.91,86.23 v1(67.18,87.5)
  L04 w0.145: v1(61.72,38.73) 62.23,39.24 63.12,39.24 64.39,37.97 75.69,37.97 81.28,43.56 81.28,53.21 80.14,54.36 80.14,68.71 69.6,79.25 69.6,85.98 68.07,87.5 v1(67.18,87.5) 67.18,90.42 65.79,91.82 65.79,97.16 64.9,98.04 64.01,98.04 63.37,98.68 63.37,99.69 v1(65.79,102.11)
MCU_REV2: length 89.5
  TOP w0.152: R3156.1 R3201.1 64.11,98.96 v1(64.14,98.93) ; U18.7 62.7,38.44 v1(62.87,38.61)
  L04 w0.145: v1(64.14,98.93) 65.02,98.93 65.53,98.42 66.29,98.42 66.55,98.17 66.55,92.08 70.36,88.27 70.36,79.38 81.28,68.45 81.28,54.61 81.92,53.98 81.92,43.31 76.07,37.47 64.01,37.47 v1(62.87,38.61)
MCU_RST: length 6.7
  TOP w0.152: U18.4 60.75,35.77 62.08,34.44 R272.1 62.97,34.44 63.12,34.29 63.12,32.61 C2523.1
MICIN: length 22.8
  TOP w0.152: R3199.1 R3200.1 16.3,20.36 19.56,23.62 27.05,23.62 28.32,24.89 28.32,25.65 28.57,25.91 29.97,25.91 30.85,26.78 U3.28
MODE: length 73.1
  TOP w0.152: v1(41.91,42.55) 39.37,42.55 39.12,42.8 33.78,42.8 33.02,42.04 28.6,42.04 R3176.1 28.7,40.92 28.7,39.5 28.42,39.21 R3177.2 28.07,38.48 28.42,38.13 29.82,38.13 30.35,37.6 U3.10 ; J24.40 55.29,87.04 v1(55.24,87)
  L04 w0.145: v1(55.24,87) 54.86,87 47.75,79.88 47.75,57.53 41.91,51.69 v1(41.91,42.55)
MSEL: length 77.2
  TOP w0.152: R3182.1 R3183.2 38.86,29.97 37.82,31.02 U3.40 35.46,31.02 v1(34.92,30.48) ; v1(53.98,89.53) 54.61,88.9 55.37,88.9 55.51,89.04 J24.50
  L04 w0.145: v1(53.98,89.53) 53.47,89.03 53.47,87.25 48.01,81.79 48.01,81.15 47.24,80.39 47.24,57.91 38.48,49.15 38.48,38.23 34.42,34.16 34.42,32.64 34.67,32.38 35.18,32.38 35.56,32 35.56,31.11 v1(34.92,30.48)
MUTEP: length 75
  TOP w0.152: v1(58.42,88.27) 58.42,88.77 58.69,89.04 J24.49 ; U3.17 v1(34.92,33.02)
  L04 w0.145: v1(58.42,88.27) 58.42,87.88 57.78,87.25 57.78,86.61 57.53,86.36 54.99,86.36 48.9,80.26 48.9,57.78 42.55,51.44 42.55,41.27 34.92,33.66 v1(34.92,33.02)
MUTER: length 70.3
  TOP w0.152: J24.37 60.17,86.64 60.45,86.36 v1(60.96,86.36) ; U3.5 32.85,37.93 34.16,39.24 34.16,40.39 35.56,41.78 38.7,41.78 39.2,41.27 43.18,41.27 v1(44.45,42.55)
  L04 w0.145: v1(60.96,86.36) 60.07,86.36 57.53,83.82 56.77,83.82 55.5,82.55 53.98,82.55 50.8,79.38 50.8,57.79 44.45,51.44 v1(44.45,42.55)
NRPIBOOT: length 3.5
  TOP w0.152: J24.93 60.35,97.84 R3156.2
OSC_IN: length 7.2
  TOP w0.203: U18.2 59.45,35.44 58.94,34.94 C2475.1 58.94,34.02 59.69,33.27 59.69,31.82 Y2.3
OSC_OUT: length 4.6
  TOP w0.203: Y2.1 60.41,33.01 C2476.1 60.41,34.97 60.1,35.28 U18.3
PI_NLED_ACTIVITY: length 5
  TOP w0.152: J24.21 59.69,83.44 60.58,82.55 61.34,82.55 62.48,81.41 D1.2
PWRSEL: length 75.8
  TOP w0.152: U3.6 32.35,38.41 R3160.2 33.5,39.21 33.66,39.37 33.66,41.05 R3173.1 33.94,42.29 38.91,42.29 39.26,41.93 42.57,41.93 v1(43.18,42.55) ; v1(62.23,86.36) 61.72,86.87 60.45,86.87 60.28,87.04 J24.39
  L04 w0.145: v1(62.23,86.36) 61.72,86.87 59.69,86.87 59.18,86.36 58.17,86.36 57.78,85.98 57.78,85.22 57.53,84.96 55.12,84.96 50.16,80.01 50.16,58.04 43.18,51.05 v1(43.18,42.55)
REG1V8: length 2.7
  TOP w0.152: C2515.1 31.85,39.18 U3.7
REG3V3: length 30.6
  TOP w0.254: C2511.1 30.61,38.61 31.35,37.87 U3.8
  TOP w0.305: R3176.2 v1(26.42,41.53) ; R3180.2 v1(21.94,30.1) ; U580.8 v1(42.8,40.26) ; R3182.2 v1(41.15,31.24) ; R3173.2 v1(30.61,41.53)
  TOP w0.381: C2511.1 C2514.1 29.31,39.21 v1(28.78,38.68)
  TOP w0.508: v1(24.77,21.34) v1(23.75,21.34) 19.94,21.34 12.71,14.11 R3158.1
RUN_PG: length 9.2
  TOP w0.152: J24.92 56.67,97.44 57.02,97.79 57.53,97.79 58.17,98.42 58.17,99.31 62.1,103.25 TP83.1
RXD0: length 63.4
  TOP w0.152: R3041.1 60.47,47.37 60.34,47.49 v1(60.34,48.13) ; R3195.1 v1(66.17,87.5)
  L04 w0.145: v1(60.34,48.13) 63.01,50.8 76.33,50.8 79.63,54.1 79.63,67.94 68.96,78.61 68.96,85.85 67.94,86.87 66.8,86.87 v1(66.17,87.5)
SCL0: length 63.3
  TOP w0.152: v1(57.15,94.61) 56.72,95.04 J24.80 ; J11.20 83.89,74.75 83.82,74.68 82.84,74.68 82.71,74.8 R16.2 81.85,74.36 81.66,74.17 79.5,74.17 v1(78.74,74.93) ; J26.20 76.77,106.75 v1(77.47,106.05)
  L03 w0.145: v1(73.79,95.89) 60.2,95.89 59.56,95.25 57.78,95.25 v1(57.15,94.61)
  L04 w0.145: v1(78.74,74.93) 76.2,77.47 76.2,92.33 73.79,94.74 v1(73.79,95.89) 73.79,102.74 77.09,106.05 v1(77.47,106.05)
SCL5: length 32.1
  TOP w0.152: J24.38 55.65,86.64 55.5,86.49 54.48,86.49 v1(53.98,87) ; U57.23 70.18,85.93 69.6,85.34 R3165.1 68.99,84.87 68.83,84.71 67.18,84.71 66.55,84.07 66.55,80.26 65.02,78.74 v1(64.14,78.74)
  L03 w0.145: v1(64.14,78.74) 57.66,78.74 56.39,80.01 54.86,80.01 53.59,81.28 53.59,86.61 v1(53.98,87)
SCL6: length 33.8
  TOP w0.152: v1(76.96,66.93) 78.28,68.25 R43.2 ; v1(60.96,88.27) 60.58,88.64 J24.47
  L04 w0.145: v1(76.96,66.93) 76.96,67.44 63.25,81.15 63.25,87 62.48,87.76 61.47,87.76 v1(60.96,88.27)
SDA0: length 66.7
  TOP w0.152: v1(78.74,73.66) 79.63,72.77 81.53,72.77 81.85,73.09 R17.2 82.69,74.25 J11.21 ; J24.82 56.83,95.44 57.02,95.25 57.78,95.25 v1(58.42,94.61) ; v1(78.74,106.05) 77.27,107.52 J26.21
  L03 w0.145: v1(58.42,94.61) 73.28,94.61 v1(74.55,95.89)
  L04 w0.145: v1(78.74,73.66) 79.38,74.3 79.38,76.71 76.96,79.12 76.96,93.09 74.55,95.5 v1(74.55,95.89) 74.55,102.74 77.22,105.41 78.11,105.41 v1(78.74,106.05)
SDA5: length 34.1
  TOP w0.152: U57.24 70.32,85.43 68.99,84.1 R3166.1 68.99,81.82 v1(65.02,77.85) ; J24.44 55.71,87.84 55.5,87.63 54.61,87.63 v1(53.98,88.27)
  L03 w0.145: v1(65.02,77.85) 55.75,77.85 54.61,78.99 54.61,79.5 52.96,81.15 52.96,87.25 v1(53.98,88.27)
SDA6: length 36.1
  TOP w0.152: J24.46 v1(55.27,88.24) ; R42.2 v1(73.66,66.29)
  L04 w0.145: v1(73.66,66.29) 73.66,67.82 62.74,78.74 62.74,86.61 62.1,87.25 60.83,87.25 59.18,88.9 58.29,88.9 57.78,88.39 57.78,87.88 57.53,87.63 55.88,87.63 v1(55.27,88.24)
SDX_CLK: length 100.5
  TOP w0.152: v1(58.42,89.53) 58.42,90.3 58.76,90.64 J24.57 ; R3141.1 v1(33.18,9.14)
  L04 w0.145: v1(33.18,9.14) 33.18,10.82 34.42,12.06 34.42,21.72 32.64,23.5 32.64,35.31 34.67,37.34 34.67,73.66 51.05,90.04 55.63,90.04 56.77,88.9 57.78,88.9 v1(58.42,89.53)
SDX_CMD: length 109
  TOP w0.152: v1(31.62,3.56) R3140.1 ; v1(53.98,93.34) 53.98,92.33 54.86,91.44 J24.62
  L04 w0.145: v1(53.98,93.34) 50.55,93.34 30.48,73.28 30.48,42.93 28.83,41.27 28.83,40.39 28.19,39.75 28.19,26.42 27.3,25.53 27.3,21.72 28.45,20.57 28.45,6.73 v1(31.62,3.56)
SDX_D0: length 106
  TOP w0.152: J24.63 60.73,91.84 v1(60.96,92.08) ; R3142.1 v1(31.62,8.26)
  L04 w0.145: v1(31.62,8.26) 30.99,8.89 30.99,10.92 33.15,13.08 33.15,20.83 31.37,22.61 31.37,36.32 33.66,38.61 33.66,74.17 50.55,91.06 56.01,91.06 56.39,91.44 58.8,91.44 59.44,92.08 v1(60.96,92.08)
SDX_D1: length 106.9
  TOP w0.152: R3143.1 v1(31.62,9.4) ; J24.67 61.66,92.64 v1(62.23,92.08)
  L04 w0.145: v1(62.23,92.08) 61.59,91.44 60.2,91.44 58.93,90.17 56.52,90.17 56.13,90.55 50.8,90.55 34.16,73.91 34.16,37.97 32,35.81 32,23.11 33.78,21.34 33.78,12.57 31.62,10.41 v1(31.62,9.4)
SDX_D2: length 114.2
  TOP w0.152: R3138.1 33.02,2.16 34.04,3.17 v1(34.04,3.56) ; J24.69 58.88,93.04 58.55,92.71 57.78,92.71 v1(57.15,93.34)
  L04 w0.145: v1(57.15,93.34) 56.52,92.71 50.67,92.71 31.24,73.28 31.24,38.35 30.1,37.21 30.1,21.46 29.08,20.45 29.08,12.45 29.97,11.56 29.97,6.1 32.51,3.56 v1(34.04,3.56)
SDX_D3: length 108.6
  TOP w0.152: R3139.1 v1(33.18,4.19) ; J24.61 57.78,91.44 v1(57.15,92.08)
  L04 w0.145: v1(33.18,4.19) 32.8,4.19 30.48,6.51 30.48,11.43 32.64,13.59 32.64,20.32 30.73,22.23 30.73,36.96 32.51,38.73 32.51,73.79 50.29,91.57 55.63,91.57 56.13,92.08 v1(57.15,92.08)
SDX_DET: length 98.6
  TOP w0.152: v1(53.98,94.61) 54.48,94.11 55.5,94.11 55.63,94.24 J24.76
  TOP w0.254: J16.9 18.19,17.08 R3132.1 v1(18.26,18.16)
  L04 w0.145: v1(53.98,94.61) 51.05,94.61 29.72,73.28 29.72,43.81 27.05,41.15 27.05,28.32 18.26,19.53 v1(18.26,18.16)
SEL: length 4.9
  TOP w0.152: U602.2 18.53,72.91 18.19,73.25 R3163.2 R3164.1 R3172.2
SWCLK: length 25.8
  TOP w0.152: U18.20 58.8,41.81 58.64,41.66 58.04,41.66 51.66,48.04 R3044.1 51.35,52.13 J7.3 51.35,60.36 TP63.1
SWDIO: length 28.6
  TOP w0.152: TP62.1 50.35,58.82 J7.2 50.35,51.97 R3043.2 51.05,50.96 51.05,47.88 57.78,41.15 58.93,41.15 59.45,41.67 U18.19
SWITCH: length 105.3
  TOP w0.152: U18.10 v1(64.65,35.43)
  TOP w0.254: v1(7.37,102.74) R3054.1 6.32,101.88 6.2,102 SW2.2
  L03 w0.145: v1(16.51,81.66) 17.02,82.17 20.32,82.17 21.21,81.28 21.84,81.28 24.77,78.36 24.77,77.22 43.56,58.42 43.56,51.18 59.31,35.43 64.64,35.43 v1(64.65,35.43)
  BOTTOM w0.152: v1(16.51,81.66) 15.11,83.06 13.34,83.06 9.27,87.12 9.27,88.9 8.76,89.41 7.62,89.41 7.24,89.79 7.24,97.92 6.35,98.81 6.35,101.73 v1(7.37,102.74)
TEST: length 6.1
  TOP w0.254: U3.20 25.83,31.52 R3181.2 25.18,30.38 25.02,30.23 23.4,30.23 R3180.1
TOUCH_INT_B: length 36
  TOP w0.152: v1(60.96,83.19) 60.71,83.19 59.65,84.24 J24.25 ; R120.2 v1(73.79,56.26)
  L04 w0.145: v1(60.96,83.19) 61.85,82.3 61.85,78.11 72.77,67.18 72.77,66.17 73.28,65.66 73.91,65.66 74.42,65.15 74.42,56.9 v1(73.79,56.26)
TP_RST: length 31.3
  TOP w0.152: v1(60.96,79.38) 60.33,78.74 58.17,78.74 57.78,79.12 57.78,83.06 57,83.84 J24.24 ; R121.2 v1(73.66,63.63)
  L04 w0.145: v1(73.66,63.63) 72.01,65.28 72.01,67.18 60.96,78.23 v1(60.96,79.38)
TXD0: length 65.4
  TOP w0.152: R3042.1 v1(59.07,48.13) ; R3194.1 v1(66.17,88.77)
  L04 w0.145: v1(66.17,88.77) 65.53,88.14 65.53,87 66.29,86.23 67.69,86.23 68.33,85.6 68.33,78.35 78.87,67.81 78.87,54.23 76.71,52.07 63.01,52.07 v1(59.07,48.13)
USB1_DM: length 33.2
  TOP w0.127: R122.1 17.08,44.99 U5.6 17.08,47.14 17.26,47.33 18.03,47.33 18.25,47.11 18.58,47.11 18.8,47.33 19.48,47.33 19.98,46.82 19.98,45.2 22.59,42.58 32.15,42.58 33.36,43.8 33.36,51.64 33.49,51.77 34.02,51.77 34.15,51.64 34.15,51.44 34.27,51.31 U600.7
USB1_DP: length 33.2
  TOP w0.127: R123.1 17.08,50.13 U5.1 17.08,47.85 17.26,47.67 19.62,47.67 20.32,46.97 20.32,45.34 22.73,42.93 32,42.93 33.02,43.94 33.02,51.79 33.35,52.11 34.02,52.11 34.15,52.24 34.15,52.45 34.27,52.58 U600.8
USB2_DM: length 39.9
  TOP w0.127: U3.44 37.4,33.02 37.48,32.94 37.66,32.94 37.89,33.17 37.89,33.48 38.12,33.71 38.43,33.71 39.14,34.42 39.47,34.42 39.68,34.63 40.01,34.63 40.23,34.42 40.56,34.42 40.77,34.63 41.1,34.63 41.32,34.42 41.65,34.42 41.87,34.63 42.2,34.63 42.41,34.42 42.74,34.42 42.96,34.63 43.29,34.63 43.5,34.42 43.83,34.42 44.05,34.63 44.38,34.63 44.6,34.42 45.24,34.42 46.48,35.66 46.48,50.44 45.32,51.6 40.42,51.6 38.06,49.23 37,49.23 36.88,49.1 36.88,48.9 36.75,48.77 U600.5
USB2_DP: length 39.9
  TOP w0.127: U3.43 37.4,32.52 37.48,32.6 37.8,32.6 39.28,34.07 45.38,34.07 46.82,35.52 46.82,50.58 45.47,51.94 40.28,51.94 37.91,49.57 37,49.57 36.88,49.7 36.88,49.91 36.75,50.04 U600.6
USB3_DM: length 4.5
  TOP w0.127: J28.4 39.06,46.61 38.98,46.69 37,46.69 36.88,46.56 36.88,46.35 36.75,46.23 U600.3
USB3_DP: length 4.5
  TOP w0.127: U600.4 36.75,47.5 36.88,47.37 36.88,47.16 37,47.03 38.98,47.03 39.06,47.11 J28.3
USB5V_AD: length 8.8
  TOP w0.381: U18.8 63.35,37.95 65.81,40.41 R3065.1 C2526.1 R3155.1 R3064.1
USB5V_AD_C: length 75.2
  TOP w0.152: v1(68.83,38.73) 68.85,38.75 R3155.2 ; J24.96 54.04,98.24 51.31,95.5 51.31,79.5 v1(52.7,78.11)
  L04 w0.145: v1(68.83,38.73) 68.83,40.89 68.2,41.53 68.2,43.69 65.53,46.35 58.29,46.35 56.77,47.88 56.77,50.42 52.58,54.61 52.58,77.98 v1(52.7,78.11)
USB_DN: length 27.6
  TOP w0.127: U602.4 17.53,72.14 17.6,72.21 17.6,72.39 17.44,72.56 17.01,72.56 16.79,72.34 16.46,72.34 16.24,72.56 15.91,72.56 15.62,72.26 15.62,72.06 15.84,71.84 15.84,71.51 15.62,71.3 15.62,70.99 15.85,70.77 15.85,70.59 15.62,70.36 15.62,69.98 15.88,69.72 16.21,69.72 16.42,69.94 16.75,69.94 16.97,69.72 17.53,69.72 17.74,69.94 18.07,69.94 18.29,69.72 18.62,69.72 18.83,69.94 19.16,69.94 19.38,69.72 19.81,69.72 20.03,69.94 20.36,69.94 20.57,69.72 21.61,69.72 21.85,69.96 21.85,70.26 22.08,70.5 22.39,70.5 22.62,70.73 22.62,71.03 22.85,71.27 23.16,71.27 23.39,71.5 23.39,71.81 23.62,72.04 23.93,72.04 24.16,72.27 24.16,72.58 24.4,72.81 24.7,72.81 24.94,73.05 24.94,73.35 25.17,73.58 25.47,73.58 26.45,74.56 26.45,75.3 26.24,75.51 26.24,75.84 26.45,76.06 26.45,76.39 26.24,76.61 26.24,76.94 26.45,77.15 26.45,77.48 26.24,77.7 26.24,78.03 26.45,78.24 26.45,78.57 26.24,78.79 26.24,79.12 26.45,79.34 26.45,79.67 26.24,79.88 25.91,79.88 25.87,79.84 J25.3
USB_DP: length 27.6
  TOP w0.127: U602.3 18.03,72.14 17.94,72.23 17.94,72.53 17.58,72.9 15.77,72.9 15.28,72.41 15.28,69.83 15.73,69.38 21.76,69.38 26.8,74.42 26.8,79.81 26.38,80.23 25.86,80.23 25.85,80.24 J25.5
USBH_DN: length 27.5
  TOP w0.127: U600.10 29.54,51.31 29.42,51.18 29.42,50.97 29.29,50.84 28.15,50.84 20.32,58.67 20.32,68.33 19.98,68.67 18.5,68.67 18.11,68.28 18.11,67.9 18.03,67.82 U602.8
USBH_DP: length 27.4
  TOP w0.127: U602.9 18.53,67.83 18.46,67.9 18.46,68.14 18.65,68.33 19.84,68.33 19.98,68.18 19.98,58.53 25.69,52.82 25.69,52.51 25.92,52.28 26.23,52.28 26.46,52.05 26.46,51.74 26.7,51.51 27,51.51 27.24,51.27 27.24,50.97 27.47,50.74 27.77,50.74 28.01,50.5 29.29,50.5 29.42,50.37 29.42,50.16 29.54,50.04 U600.11
USBOTG_ID: length 10.4
  TOP w0.152: R3172.1 17.37,78.08 17.65,78.36 Q7.3 TP94.1 22.99,78.36 24.07,79.44 J25.1
USBS_DN: length 11.2
  TOP w0.127: R3161.2 10.91,70.38 11.45,69.84 U601.4 11.45,68.16 11.65,67.96 13.57,67.96 13.9,67.63 13.9,67.51 14.13,67.28 14.44,67.28 14.67,67.04 14.67,66.74 14.91,66.5 15.21,66.5 15.45,66.27 15.45,65.96 15.75,65.66 16.99,65.66 17.11,65.79 17.11,66.03 17.03,66.11 U602.6
USBS_DP: length 11.3
  TOP w0.127: U602.7 17.53,66.11 17.46,66.03 17.46,65.64 17.13,65.32 15.61,65.32 13.55,67.37 13.55,67.49 13.43,67.61 11.57,67.61 11.45,67.49 U601.3 11.45,65.93 10.91,65.39 R3162.2
VBIAS: length 18.3
  TOP w0.152: U3.26 29.85,27.05 29.59,26.8 21.46,26.8 16.55,21.88 R3190.1
VD33: length 4.5
  TOP w0.381: U600.12 v1(28.83,48.77)
  L04 w0.381: v1(28.83,48.77) v1(28.83,46.23)
VLED+:
  vias: v1(51.98,6.1) v1(51.98,5.08) v1(52.99,6.1) v1(52.99,5.08) v1(54.01,6.1) v1(54.01,5.08) v1(81.82,30.23) v1(82.84,30.23) v1(83.85,30.23) v1(84.74,30.23)
VLED-:
  vias: v1(53.75,12.95) v1(53.75,11.94) v1(55.02,12.95) v1(55.02,11.94) v1(81.82,32.51) v1(82.84,32.51) v1(83.85,32.51)
VOLDN: length 72.9
  TOP w0.152: U3.47 37.44,34.52 38.48,35.56 v1(44.45,35.56) ; v1(58.42,81.92) 58.42,83.06 57.78,83.69 57.78,89.66 57.21,90.24 J24.56
  L04 w0.145: v1(58.42,81.92) 56.52,81.92 55.88,81.28 53.72,81.28 51.31,78.87 51.31,57.4 45.97,52.07 45.97,37.08 v1(44.45,35.56)
VOLUP: length 72.1
  TOP w0.152: v1(34.92,31.75) 35.16,31.52 U3.41 ; v1(52.7,88.27) 53.34,88.9 53.34,89.79 54.19,90.64 J24.58
  L04 w0.145: v1(52.7,88.27) 50.8,86.36 50.8,85.47 47.62,82.3 46.86,82.3 45.59,81.03 45.59,57.28 37.85,49.53 37.85,38.61 33.78,34.54 33.78,32.38 34.42,31.75 v1(34.92,31.75)
WL_NDIS: length 4.8
  TOP w0.152: TP77.1 63.01,97.04 J24.89
N1478133: length 11.5
  TOP w0.152: R42.1 R114.1 77.34,65.02 78.23,64.14 80.77,64.14 81.31,63.6 D11.C
  TOP w0.254: J17.2 82.01,61.75 81.31,62.45 D11.C
N1478157: length 8
  TOP w0.152: R43.1 R115.1 80.58,66.36 81.31,65.63 D12.C
  TOP w0.254: J17.1 83.03,62.25 82.42,62.87 82.42,64.77 82.12,65.07 D12.C
N1478281: length 12.6
  TOP w0.152: D14.C 80.69,61.01 80.01,60.33 77.47,60.33 76.96,60.83 C81.1 76.2,61.5 R117.2 R121.1 TP28.1
  TOP w0.254: D14.C 82.5,61.01 82.76,60.75 J17.4
N1478289: length 13.9
  TOP w0.152: TP29.1 R120.1 R118.2 76.2,58.52 C82.1 76.96,59.18 77.47,59.69 79.88,59.69 80.6,58.97 D13.C
  TOP w0.254: J17.5 81.72,60.25 81.31,59.85 D13.C
N12332208: length 10.6
  TOP w0.381: J9.2 77.74,96.8 U12.5 77.5,96.56 R125.1 TP60.1
N12332215: length 11.4
  TOP w0.381: J9.1 82.79,97.8 80.01,100.58 U12.8 77.71,101.09 77.96,101.35 78.74,101.35 TP61.1
N12333733: length 3.8
  TOP w0.381: Q6.3 70.49,100.46 R124.2 71.47,100.43 71.63,100.58 U12.1
N12334307: length 5.9
  TOP w0.508: U12.2 71.12,99.31 70.39,98.58 C86.1 70.64,98.04 U12.3
N12334479: length 5.4
  TOP w0.381: U12.4 74.8,96.77 75.21,96.36 R126.1 R125.2
N12334672: length 1.5
  TOP w0.381: R126.2 C87.2
N12335205: length 3.2
  TOP w0.381: TP58.1 69.88,96.49 R127.2 C87.1
N12373140: length 1.8
  TOP w0.152: R368.2 71.51,82.94 U57.1
N12374321: length 3.7
  TOP w0.152: R370.2 C383.1 76.68,85.78 76.53,85.93 U57.8
N12375648: length 2.3
  TOP w0.152: C384.1 75.73,86.93 U57.10
N12375668: length 3.3
  TOP w0.152: U57.11 75.49,87.43 75.95,87.88 75.95,89 76.1,89.15 R371.2
N12378079: length 1.8
  TOP w0.152: U57.20 69.02,87.43 C386.2
